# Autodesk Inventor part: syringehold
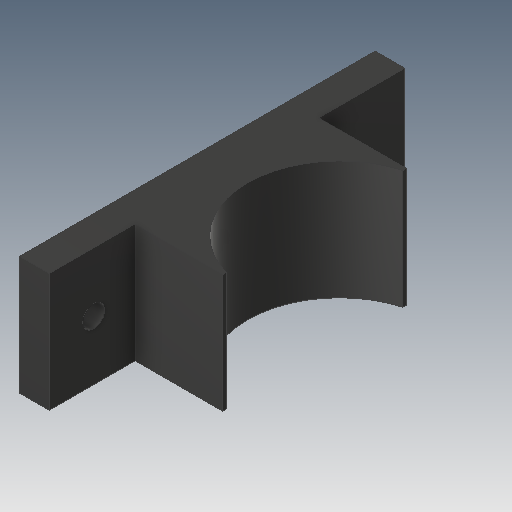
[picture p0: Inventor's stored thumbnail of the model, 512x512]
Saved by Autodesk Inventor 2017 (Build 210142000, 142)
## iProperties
Created: 2018-08
Part Number: syringehold
Material: Plastic, Opaque Black
Document SubType Name: Modeling
Designer: JK
Density: 0.952 g/cm^3
Appearance: Smooth - Black
Author: JK
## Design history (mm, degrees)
sketch "Sketch1"
  geometry: L1 (14.819, 27.763)-(9.819, 27.763); L2 (9.819, 27.763)-(9.819, -32.237); L3 (9.819, -32.237)-(14.819, -32.237); L4 (14.819, -32.237)-(14.819, 27.763); L5 (9.819, 13.263)-(-8.59, 13.263); L6 (-9.181, -17.726)-(9.819, -17.726); L7 (9.819, -17.726)-(9.819, 13.263); A1 r 15.5 centre (-9.181, -2.226) between (-9.181, -17.726) and (-8.59, 13.263); 1 further point
  constraints: 14 end point, 3 parallel, 2 horizontal, 2 point on circle, 1 centre point, 1 collinear, 1 perpendicular, 1 point on line, 1 tangent
  dimensions: "d0" = 60 distance of L3.end L1.start; "d1" = 31 diameter of A1; "d4" = 14.5 distance between parallel lines of L1 L5; "d16" = 5 distance of L2.end L3.end; "d17" = 24 distance from line of L4 A1.centre
extrude "Extrusion1" new body sketch "Sketch1" distance "d5" = 20; taper "d6" = 0 deg
sketch "Sketch2"
  geometry: L1 (60, 0)-(60, 20) reference; L2 (0, 0)-(0, 20) reference; L3 (0, 20)-(60, 20) reference; C1 r 1.85 at (52.5, 10); C2 r 1.85 at (7.5, 10); 1 further point
  constraints: 2 centre point, 1 horizontal alignment
  dimensions: "d7" = 3.7 diameter of C1; "d8" = 3.7 diameter of C2; "d9" = 7.5 distance from line of L1 C1.centre; "d10" = 7.5 distance from line of L2 C2.centre; "d11" = 10 distance from line of L3 C2.centre
extrude "Extrusion2" cut sketch "Sketch2" distance "d12" = 20; taper "d13" = 0 deg
sketch "Sketch3"
  geometry: L1 (4.971, -22.921)-(19.821, -22.921); L2 (19.821, -22.921)-(19.821, 29.621); L3 (19.821, 29.621)-(4.971, 29.621); L4 (4.971, 29.621)-(4.971, -22.921); 1 further point
  constraints: 8 end point, 2 parallel, 1 horizontal, 1 perpendicular
extrude "Extrusion3" cut sketch "Sketch3" stored distance "d14" = 0; taper "d15" = 0 deg
body "Solid1"
